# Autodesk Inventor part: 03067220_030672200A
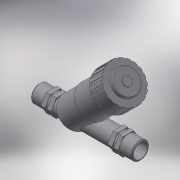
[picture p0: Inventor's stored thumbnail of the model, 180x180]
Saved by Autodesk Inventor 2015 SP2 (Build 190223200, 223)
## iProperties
Created: 2017-05
Part Number: 03067220_030672200A
Material: Generic
Description: PLASSON CHECK VALVE 2"
Document SubType Name: Modeling
Designer: KIM
Mass: 228.741 g
Surface Area: 415.565 cm^2
Volume: 228.741 cm^3
Density: 1 g/cm^3
Appearance: Default
Author: KIM
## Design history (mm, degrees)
derived "03067-03068.ipt"
feature "Solid1::03067-03068.ipt"
tag "TaggingFeature1"
body "Solid1"
other parameters: "d0" = 254, "d1" = 59.614, "d2" = 65, "d3" = 47.6912, "d4" = 26, "d5" = 26, "d6" = 25.4, "d8" = 2.54, "d12" = 0, "d14" = -12.7, "d15" = 5.08, "d16" = 0, "d17" = 68.796, "d18" = 9.828, "d20" = 85.995, "d21" = 135 deg, "d22" = 90.09, "d23" = 49.14, "d24" = 106.47, "d25" = 24.57, "d29" = 24.57, "d31" = 24.57, "d32" = 81.9, "d34" = 135 deg, "d35" = 2, "d36" = 163.8, "d39" = 88.9, "d40" = 3.64, "d80" = 103.2759, "d81" = 7.28, "d82" = 3.64, "d83" = 42.588, "d84" = 0, "d86" = 360 deg, "d88" = 1.82, "d90" = 1, "d91" = 182, "d92" = 2.457, "H_" = 254, "R_" = 59.614, "E_" = 65, "l_2" = 26, "A_" = 182, "d13" = 25.4, "d79" = 106.47
